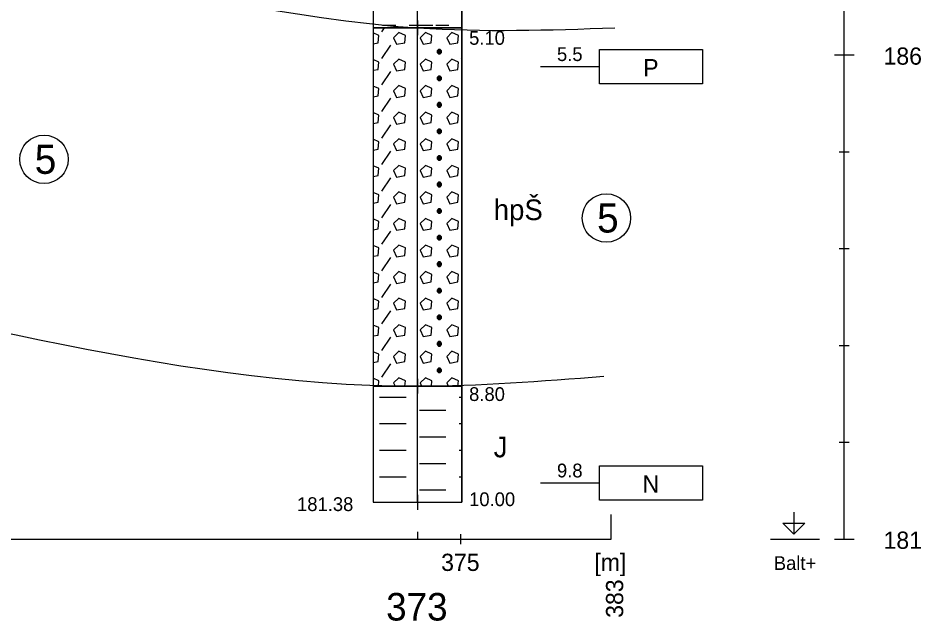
# Model space of a CAD drawing. Extents: x 3042 to 4120, y 576 to 2694.
# Drawn here: x 3598.44 to 3645.09, y 860.63 to 891.76 of the extents above; entities that cross this region are included whole.
import ezdxf

# ---------------------------------------------------------------- set-up
doc = ezdxf.new("R2010")
doc.units = 0
for name, color, linetype in [('12', 7, 'Continuous'), ('14', 7, 'Continuous'), ('17', 7, 'Continuous'), ('18', 7, 'Continuous'), ('19', 7, 'Continuous'), ('21', 7, 'Continuous'), ('51', 7, 'Continuous'), ('52', 7, 'Continuous'), ('53', 7, 'Continuous'), ('56', 7, 'Continuous'), ('62', 7, 'Continuous'), ('7', 7, 'Continuous'), ('rozhraní', 7, 'Continuous')]:
    doc.layers.add(name, color=color, linetype=linetype)

msp = doc.modelspace()

# ---------------------------------------------------------------- linework, layer by layer
at = {"layer": '12'}
msp.add_line((3629.082, 864.859), (3629.082, 866.129), dxfattribs=at)
at = {"layer": '18'}
for p, q in [((3619.082, 866.759), (3619.082, 916.759)), ((3619.082, 867.14), (3619.082, 866.378)), ((3618.701, 866.759), (3619.463, 866.759)), ((3619.082, 865.24), (3619.082, 864.859))]:
    msp.add_line(p, q, dxfattribs=at)
at = {"layer": '19'}
for p, q in [((3640.624, 889.859), (3641.64, 889.859)), ((3640.878, 884.859), (3641.386, 884.859)), ((3640.878, 879.859), (3641.386, 879.859)), ((3640.878, 874.859), (3641.386, 874.859)), ((3640.878, 869.859), (3641.386, 869.859)), ((3640.624, 864.859), (3641.64, 864.859))]:
    msp.add_line(p, q, dxfattribs=at)
at = {"layer": '21'}
for p, q in [((3641.132, 864.859), (3641.132, 924.859)), ((3637.322, 864.859), (3639.862, 864.859))]:
    msp.add_line(p, q, dxfattribs=at)
msp.add_lwpolyline([(3638.528, 866.256), (3638.528, 865.113), (3637.957, 865.685), (3639.1, 865.685), (3638.528, 865.113)], dxfattribs=at)
at = {"layer": '51'}
for p, q in [((3617.24, 891.055), (3617.376, 891.259)), ((3617.278, 891.398), (3617.964, 891.398)), ((3618.65, 891.398), (3619.336, 891.398)), ((3619.183, 891.398), (3619.869, 891.398)), ((3620.022, 891.398), (3620.707, 891.398)), ((3621.355, 891.055), (3621.368, 891.074)), ((3617.24, 889.684), (3617.697, 890.37)), ((3620.212, 889.912), (3620.212, 890.141)), ((3621.355, 889.684), (3621.368, 889.703)), ((3617.24, 888.312), (3617.697, 888.998)), ((3620.212, 888.541), (3620.212, 888.769)), ((3621.355, 888.312), (3621.368, 888.331)), ((3617.24, 886.941), (3617.697, 887.626)), ((3620.212, 887.169), (3620.212, 887.398)), ((3621.355, 886.941), (3621.368, 886.96)), ((3617.24, 885.569), (3617.697, 886.255)), ((3620.212, 885.798), (3620.212, 886.026)), ((3621.355, 885.569), (3621.368, 885.588)), ((3617.24, 884.197), (3617.697, 884.883)), ((3620.212, 884.426), (3620.212, 884.655)), ((3621.355, 884.197), (3621.368, 884.216)), ((3617.24, 882.826), (3617.697, 883.512)), ((3620.212, 883.054), (3620.212, 883.283)), ((3621.355, 882.826), (3621.368, 882.845)), ((3617.24, 881.454), (3617.697, 882.14)), ((3620.212, 881.683), (3620.212, 881.911)), ((3621.355, 881.454), (3621.368, 881.473)), ((3617.24, 880.083), (3617.697, 880.768)), ((3620.212, 880.311), (3620.212, 880.54)), ((3621.355, 880.083), (3621.368, 880.102)), ((3617.24, 878.711), (3617.697, 879.397)), ((3620.212, 878.94), (3620.212, 879.168)), ((3621.355, 878.711), (3621.368, 878.73)), ((3617.24, 877.34), (3617.697, 878.025)), ((3620.212, 877.568), (3620.212, 877.797)), ((3621.355, 877.34), (3621.368, 877.358)), ((3617.24, 875.968), (3617.697, 876.654)), ((3620.212, 876.197), (3620.212, 876.425)), ((3621.355, 875.968), (3621.368, 875.987)), ((3617.24, 874.596), (3617.697, 875.282)), ((3620.212, 874.825), (3620.212, 875.054)), ((3621.355, 874.596), (3621.368, 874.615)), ((3617.24, 873.225), (3617.697, 873.911)), ((3620.212, 873.453), (3620.212, 873.682)), ((3617.85, 872.92), (3617.921, 872.759)), ((3619.221, 872.92), (3619.293, 872.759)), ((3620.593, 872.92), (3620.665, 872.759)), ((3621.355, 873.225), (3621.368, 873.244)), ((3617.126, 872.196), (3617.812, 872.196)), ((3617.812, 872.196), (3618.498, 872.196)), ((3621.241, 872.196), (3621.368, 872.196)), ((3619.183, 871.51), (3619.869, 871.51)), ((3619.869, 871.51), (3620.555, 871.51)), ((3617.126, 870.824), (3617.812, 870.824)), ((3617.812, 870.824), (3618.498, 870.824)), ((3621.241, 870.824), (3621.368, 870.824)), ((3619.183, 870.139), (3619.869, 870.139)), ((3619.869, 870.139), (3620.555, 870.139)), ((3617.126, 869.453), (3617.812, 869.453)), ((3617.812, 869.453), (3618.498, 869.453)), ((3621.241, 869.453), (3621.368, 869.453)), ((3619.183, 868.767), (3619.869, 868.767)), ((3619.869, 868.767), (3620.555, 868.767)), ((3617.126, 868.081), (3617.812, 868.081)), ((3617.812, 868.081), (3618.498, 868.081)), ((3621.241, 868.081), (3621.368, 868.081)), ((3619.183, 867.395), (3619.869, 867.395)), ((3619.869, 867.395), (3620.555, 867.395))]:
    msp.add_line(p, q, dxfattribs=at)
for points in [[(3616.796, 891.259), (3621.368, 891.259), (3621.368, 894.759), (3616.796, 894.759)], [(3616.796, 872.759), (3621.368, 872.759), (3621.368, 891.259), (3616.796, 891.259)], [(3616.796, 866.759), (3621.368, 866.759), (3621.368, 872.759), (3616.796, 872.759)]]:
    msp.add_lwpolyline(points, close=True, dxfattribs=at)
for points in [[(3616.796, 890.438), (3617.05, 890.484), (3617.088, 890.865), (3616.796, 890.995)], [(3617.85, 890.751), (3618.002, 890.408), (3618.421, 890.484), (3618.459, 890.865), (3618.117, 891.017), (3617.85, 890.751)], [(3619.221, 890.751), (3619.374, 890.408), (3619.793, 890.484), (3619.831, 890.865), (3619.488, 891.017), (3619.221, 890.751)], [(3620.593, 890.751), (3620.745, 890.408), (3621.165, 890.484), (3621.203, 890.865), (3620.86, 891.017), (3620.593, 890.751)], [(3620.174, 890.141), (3620.098, 890.065), (3620.098, 889.989), (3620.174, 889.912), (3620.25, 889.912), (3620.326, 889.989), (3620.326, 890.065), (3620.25, 890.141), (3620.174, 890.141), (3620.326, 889.989), (3620.098, 889.989), (3620.25, 890.141)], [(3617.85, 889.379), (3618.002, 889.036), (3618.421, 889.112), (3618.459, 889.493), (3618.117, 889.646), (3617.85, 889.379)], [(3619.221, 889.379), (3619.374, 889.036), (3619.793, 889.112), (3619.831, 889.493), (3619.488, 889.646), (3619.221, 889.379)], [(3620.593, 889.379), (3620.745, 889.036), (3621.165, 889.112), (3621.203, 889.493), (3620.86, 889.646), (3620.593, 889.379)], [(3616.796, 889.066), (3617.05, 889.112), (3617.088, 889.493), (3616.796, 889.623)], [(3620.174, 888.769), (3620.098, 888.693), (3620.098, 888.617), (3620.174, 888.541), (3620.25, 888.541), (3620.326, 888.617), (3620.326, 888.693), (3620.25, 888.769), (3620.174, 888.769), (3620.326, 888.617), (3620.098, 888.617), (3620.25, 888.769)], [(3616.796, 887.695), (3617.05, 887.741), (3617.088, 888.122), (3616.796, 888.252)], [(3617.85, 888.007), (3618.002, 887.665), (3618.421, 887.741), (3618.459, 888.122), (3618.117, 888.274), (3617.85, 888.007)], [(3619.221, 888.007), (3619.374, 887.665), (3619.793, 887.741), (3619.831, 888.122), (3619.488, 888.274), (3619.221, 888.007)], [(3620.593, 888.007), (3620.745, 887.665), (3621.165, 887.741), (3621.203, 888.122), (3620.86, 888.274), (3620.593, 888.007)], [(3620.174, 887.398), (3620.098, 887.322), (3620.098, 887.245), (3620.174, 887.169), (3620.25, 887.169), (3620.326, 887.245), (3620.326, 887.322), (3620.25, 887.398), (3620.174, 887.398), (3620.326, 887.245), (3620.098, 887.245), (3620.25, 887.398)], [(3616.796, 886.323), (3617.05, 886.369), (3617.088, 886.75), (3616.796, 886.88)], [(3617.85, 886.636), (3618.002, 886.293), (3618.421, 886.369), (3618.459, 886.75), (3618.117, 886.903), (3617.85, 886.636)], [(3619.221, 886.636), (3619.374, 886.293), (3619.793, 886.369), (3619.831, 886.75), (3619.488, 886.903), (3619.221, 886.636)], [(3620.593, 886.636), (3620.745, 886.293), (3621.165, 886.369), (3621.203, 886.75), (3620.86, 886.903), (3620.593, 886.636)], [(3620.174, 886.026), (3620.098, 885.95), (3620.098, 885.874), (3620.174, 885.798), (3620.25, 885.798), (3620.326, 885.874), (3620.326, 885.95), (3620.25, 886.026), (3620.174, 886.026), (3620.326, 885.874), (3620.098, 885.874), (3620.25, 886.026)], [(3616.796, 884.951), (3617.05, 884.998), (3617.088, 885.379), (3616.796, 885.508)], [(3617.85, 885.264), (3618.002, 884.921), (3618.421, 884.998), (3618.459, 885.379), (3618.117, 885.531), (3617.85, 885.264)], [(3619.221, 885.264), (3619.374, 884.921), (3619.793, 884.998), (3619.831, 885.379), (3619.488, 885.531), (3619.221, 885.264)], [(3620.593, 885.264), (3620.745, 884.921), (3621.165, 884.998), (3621.203, 885.379), (3620.86, 885.531), (3620.593, 885.264)], [(3620.174, 884.655), (3620.098, 884.578), (3620.098, 884.502), (3620.174, 884.426), (3620.25, 884.426), (3620.326, 884.502), (3620.326, 884.578), (3620.25, 884.655), (3620.174, 884.655), (3620.326, 884.502), (3620.098, 884.502), (3620.25, 884.655)], [(3616.796, 883.58), (3617.05, 883.626), (3617.088, 884.007), (3616.796, 884.137)], [(3617.85, 883.893), (3618.002, 883.55), (3618.421, 883.626), (3618.459, 884.007), (3618.117, 884.159), (3617.85, 883.893)], [(3619.221, 883.893), (3619.374, 883.55), (3619.793, 883.626), (3619.831, 884.007), (3619.488, 884.159), (3619.221, 883.893)], [(3620.593, 883.893), (3620.745, 883.55), (3621.165, 883.626), (3621.203, 884.007), (3620.86, 884.159), (3620.593, 883.893)], [(3620.174, 883.283), (3620.098, 883.207), (3620.098, 883.131), (3620.174, 883.054), (3620.25, 883.054), (3620.326, 883.131), (3620.326, 883.207), (3620.25, 883.283), (3620.174, 883.283), (3620.326, 883.131), (3620.098, 883.131), (3620.25, 883.283)], [(3616.796, 882.208), (3617.05, 882.254), (3617.088, 882.635), (3616.796, 882.765)], [(3617.85, 882.521), (3618.002, 882.178), (3618.421, 882.254), (3618.459, 882.635), (3618.117, 882.788), (3617.85, 882.521)], [(3619.221, 882.521), (3619.374, 882.178), (3619.793, 882.254), (3619.831, 882.635), (3619.488, 882.788), (3619.221, 882.521)], [(3620.593, 882.521), (3620.745, 882.178), (3621.165, 882.254), (3621.203, 882.635), (3620.86, 882.788), (3620.593, 882.521)], [(3620.174, 881.911), (3620.098, 881.835), (3620.098, 881.759), (3620.174, 881.683), (3620.25, 881.683), (3620.326, 881.759), (3620.326, 881.835), (3620.25, 881.911), (3620.174, 881.911), (3620.326, 881.759), (3620.098, 881.759), (3620.25, 881.911)], [(3616.796, 880.837), (3617.05, 880.883), (3617.088, 881.264), (3616.796, 881.394)], [(3617.85, 881.149), (3618.002, 880.807), (3618.421, 880.883), (3618.459, 881.264), (3618.117, 881.416), (3617.85, 881.149)], [(3619.221, 881.149), (3619.374, 880.807), (3619.793, 880.883), (3619.831, 881.264), (3619.488, 881.416), (3619.221, 881.149)], [(3620.593, 881.149), (3620.745, 880.807), (3621.165, 880.883), (3621.203, 881.264), (3620.86, 881.416), (3620.593, 881.149)], [(3620.174, 880.54), (3620.098, 880.464), (3620.098, 880.387), (3620.174, 880.311), (3620.25, 880.311), (3620.326, 880.387), (3620.326, 880.464), (3620.25, 880.54), (3620.174, 880.54), (3620.326, 880.387), (3620.098, 880.387), (3620.25, 880.54)], [(3616.796, 879.465), (3617.05, 879.511), (3617.088, 879.892), (3616.796, 880.022)], [(3617.85, 879.778), (3618.002, 879.435), (3618.421, 879.511), (3618.459, 879.892), (3618.117, 880.045), (3617.85, 879.778)], [(3619.221, 879.778), (3619.374, 879.435), (3619.793, 879.511), (3619.831, 879.892), (3619.488, 880.045), (3619.221, 879.778)], [(3620.593, 879.778), (3620.745, 879.435), (3621.165, 879.511), (3621.203, 879.892), (3620.86, 880.045), (3620.593, 879.778)], [(3620.174, 879.168), (3620.098, 879.092), (3620.098, 879.016), (3620.174, 878.94), (3620.25, 878.94), (3620.326, 879.016), (3620.326, 879.092), (3620.25, 879.168), (3620.174, 879.168), (3620.326, 879.016), (3620.098, 879.016), (3620.25, 879.168)], [(3616.796, 878.093), (3617.05, 878.14), (3617.088, 878.521), (3616.796, 878.65)], [(3617.85, 878.406), (3618.002, 878.063), (3618.421, 878.14), (3618.459, 878.521), (3618.117, 878.673), (3617.85, 878.406)], [(3619.221, 878.406), (3619.374, 878.063), (3619.793, 878.14), (3619.831, 878.521), (3619.488, 878.673), (3619.221, 878.406)], [(3620.593, 878.406), (3620.745, 878.063), (3621.165, 878.14), (3621.203, 878.521), (3620.86, 878.673), (3620.593, 878.406)], [(3620.174, 877.797), (3620.098, 877.721), (3620.098, 877.644), (3620.174, 877.568), (3620.25, 877.568), (3620.326, 877.644), (3620.326, 877.721), (3620.25, 877.797), (3620.174, 877.797), (3620.326, 877.644), (3620.098, 877.644), (3620.25, 877.797)], [(3616.796, 876.722), (3617.05, 876.768), (3617.088, 877.149), (3616.796, 877.279)], [(3617.85, 877.035), (3618.002, 876.692), (3618.421, 876.768), (3618.459, 877.149), (3618.117, 877.301), (3617.85, 877.035)], [(3619.221, 877.035), (3619.374, 876.692), (3619.793, 876.768), (3619.831, 877.149), (3619.488, 877.301), (3619.221, 877.035)], [(3620.593, 877.035), (3620.745, 876.692), (3621.165, 876.768), (3621.203, 877.149), (3620.86, 877.301), (3620.593, 877.035)], [(3620.174, 876.425), (3620.098, 876.349), (3620.098, 876.273), (3620.174, 876.197), (3620.25, 876.197), (3620.326, 876.273), (3620.326, 876.349), (3620.25, 876.425), (3620.174, 876.425), (3620.326, 876.273), (3620.098, 876.273), (3620.25, 876.425)], [(3616.796, 875.35), (3617.05, 875.396), (3617.088, 875.777), (3616.796, 875.907)], [(3617.85, 875.663), (3618.002, 875.32), (3618.421, 875.396), (3618.459, 875.777), (3618.117, 875.93), (3617.85, 875.663)], [(3619.221, 875.663), (3619.374, 875.32), (3619.793, 875.396), (3619.831, 875.777), (3619.488, 875.93), (3619.221, 875.663)], [(3620.593, 875.663), (3620.745, 875.32), (3621.165, 875.396), (3621.203, 875.777), (3620.86, 875.93), (3620.593, 875.663)], [(3620.174, 875.054), (3620.098, 874.977), (3620.098, 874.901), (3620.174, 874.825), (3620.25, 874.825), (3620.326, 874.901), (3620.326, 874.977), (3620.25, 875.054), (3620.174, 875.054), (3620.326, 874.901), (3620.098, 874.901), (3620.25, 875.054)], [(3616.796, 873.979), (3617.05, 874.025), (3617.088, 874.406), (3616.796, 874.536)], [(3617.85, 874.292), (3618.002, 873.949), (3618.421, 874.025), (3618.459, 874.406), (3618.117, 874.558), (3617.85, 874.292)], [(3619.221, 874.292), (3619.374, 873.949), (3619.793, 874.025), (3619.831, 874.406), (3619.488, 874.558), (3619.221, 874.292)], [(3620.593, 874.292), (3620.745, 873.949), (3621.165, 874.025), (3621.203, 874.406), (3620.86, 874.558), (3620.593, 874.292)], [(3620.174, 873.682), (3620.098, 873.606), (3620.098, 873.53), (3620.174, 873.453), (3620.25, 873.453), (3620.326, 873.53), (3620.326, 873.606), (3620.25, 873.682), (3620.174, 873.682), (3620.326, 873.53), (3620.098, 873.53), (3620.25, 873.682)], [(3617.06, 872.759), (3617.088, 873.034), (3616.796, 873.164)], [(3618.432, 872.759), (3618.459, 873.034), (3618.117, 873.187), (3617.85, 872.92)], [(3619.804, 872.759), (3619.831, 873.034), (3619.488, 873.187), (3619.221, 872.92)], [(3621.175, 872.759), (3621.203, 873.034), (3620.86, 873.187), (3620.593, 872.92)]]:
    msp.add_lwpolyline(points, dxfattribs=at)
at = {"layer": '53'}
for p, q in [((3616.796, 916.759), (3616.796, 866.759)), ((3621.368, 916.759), (3621.368, 866.759)), ((3616.796, 891.259), (3621.368, 891.259)), ((3616.796, 872.759), (3621.368, 872.759)), ((3616.796, 866.759), (3621.368, 866.759))]:
    msp.add_line(p, q, dxfattribs=at)
at = {"layer": '56'}
for p, q in [((3619.082, 891.64), (3619.082, 890.878)), ((3618.701, 891.259), (3619.463, 891.259)), ((3619.082, 873.14), (3619.082, 872.378)), ((3618.701, 872.759), (3619.463, 872.759)), ((3619.082, 867.14), (3619.082, 866.378)), ((3618.701, 866.759), (3619.463, 866.759))]:
    msp.add_line(p, q, dxfattribs=at)
at = {"layer": '62'}
for p, q in [((3625.432, 889.259), (3628.48, 889.259)), ((3625.432, 867.759), (3628.48, 867.759))]:
    msp.add_line(p, q, dxfattribs=at)
for points in [[(3633.814, 888.37), (3628.48, 888.37), (3628.48, 890.148), (3633.814, 890.148), (3633.814, 888.37)], [(3633.814, 866.87), (3628.48, 866.87), (3628.48, 868.648), (3633.814, 868.648), (3633.814, 866.87)]]:
    msp.add_lwpolyline(points, dxfattribs=at)
at = {"layer": '7'}
for p, q in [((3621.322, 864.605), (3621.322, 865.113)), ((3246.322, 864.859), (3629.082, 864.859))]:
    msp.add_line(p, q, dxfattribs=at)
at = {"layer": 'rozhraní'}
for centre in [(3599.786, 884.47), (3628.842, 881.439)]:
    msp.add_circle(centre, 1.25, dxfattribs=at)
for points in [[(3248.314, 891.859), (3256.322, 891.859), (3352.572, 886.409), (3431.332, 884.009), (3453.062, 885.409), (3491.522, 887.359), (3557.332, 884.659), (3580.052, 895.009), (3619.082, 891.259), (3629.275, 891.259)], [(3311.777, 872.826), (3352.572, 872.409), (3453.062, 876.909), (3491.522, 872.859), (3557.332, 880.159), (3580.052, 879.009), (3619.082, 872.759), (3628.717, 873.273)]]:
    msp.add_spline(points, degree=3, dxfattribs=at)

# ---------------------------------------------------------------- texts
at = {"layer": '12'}
msp.add_text('383', height=0.889, rotation=90, dxfattribs=at).set_placement((3629.71, 860.795))
at = {"layer": '14'}
msp.add_text('373', height=1.4224, dxfattribs=at).set_placement((3617.462, 860.653))
at = {"layer": '17'}
msp.add_text('181.38', height=0.7112, dxfattribs=at).set_placement((3612.859, 866.307))
at = {"layer": '19'}
for s, p in [('186', (3643.164, 889.357)), ('181', (3643.164, 864.357))]:
    msp.add_text(s, height=0.889, dxfattribs=at).set_placement(p)
at = {"layer": '21'}
msp.add_text('Balt+', height=0.7112, dxfattribs=at).set_placement((3637.491, 863.264))
at = {"layer": '52'}
for s, height, p in [('5.10', 0.7112, (3621.749, 890.384)), ('hpŠ', 1.0668, (3623.019, 881.331)), ('8.80', 0.7112, (3621.749, 871.99)), ('J', 1.067, (3623.019, 869.081)), ('10.00', 0.7112, (3621.749, 866.561))]:
    msp.add_text(s, height=height, dxfattribs=at).set_placement(p)
at = {"layer": '62'}
for s, height, p in [('5.5', 0.7112, (3626.289, 889.544)), ('P', 0.889, (3630.745, 888.757)), ('9.8', 0.7112, (3626.289, 868.044)), ('N', 0.889, (3630.713, 867.257))]:
    msp.add_text(s, height=height, dxfattribs=at).set_placement(p)
at = {"layer": '7'}
for s, p in [('375', (3620.306, 863.214)), ('[m]', (3628.224, 863.214))]:
    msp.add_text(s, height=0.889, dxfattribs=at).set_placement(p)
at = {"layer": 'rozhraní'}
for p in [(3599.305, 883.72), (3628.361, 880.689)]:
    msp.add_text('5', height=1.5, dxfattribs=at).set_placement(p)

doc.saveas('drawing.dxf')
